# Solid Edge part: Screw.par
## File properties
Title: Screw
Author: Robert a Rhodes jr
Template: Normal.par
Last saved by: TIET
Revision: 10
Application: Solid Edge
Accuracy: 0.99
Material: aluminum
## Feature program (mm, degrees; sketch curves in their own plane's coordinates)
sketch for "unnamed Protrusion 1" plane through (0, 0, 0) normal (0, -1, 0) x-axis (1, 0, 0)
  circle centre (0, 0) radius 12.5
extrude "unnamed Protrusion 1" add finite 25 along +normal
sketch for "ExtrudedProtrusion_2" plane through (0, -25, 0) normal (0, -1, 0) x-axis (1, 0, 0)
  circle centre (0, 0) radius 10
extrude "ExtrudedProtrusion_2" add finite 96 along +normal
sketch for "ExtrudedProtrusion_3" plane through (0, -121, 0) normal (0, -1, 0) x-axis (1, 0, 0)
  circle centre (0, 0) radius 6
extrude "ExtrudedProtrusion_3" add finite 4 along +normal
sketch for "ExtrudedProtrusion_4" plane through (0, -125, 0) normal (0, -1, 0) x-axis (1, 0, 0)
  circle centre (0, 0) radius 4
extrude "ExtrudedProtrusion_4" add finite 6 along +normal
sketch for "unnamed RevolvedProtrusion 1" plane through (0, 0, 0) normal (0, 0, 1) x-axis (1, 0, 0)
  line (0, -131) -> (6, -131)
  line (6, -131) -> (6, -141)
  line (6, -141) -> (0, -143.8522)
  line (0, -143.8522) -> (0, -131)
revolve "unnamed RevolvedProtrusion 1" add full turn 360 deg about sketch line (0, -131) -> (0, -106.3065)
sketch for "ExtrudedCutout_1" plane through (0, 0, 0) normal (1, 0, 0) x-axis (0, 1, 0)
  circle centre (-13, 0) radius 5.5
extrude "ExtrudedCutout_1" cut finite 222.1 symmetric
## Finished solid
Body 1: solid body, 12 faces, 12 edges, 1 vertex.
  Faces by surface: cylinder 6, plane 5, cone 1
  Edges by curve: circle 10, intersection 2
Bounding box of the edges (mm): 25.000 x 141.000 x 25.000, from (-12.5, -141, -12.5) to (12.5, 0, 12.5).
Cylindrical faces by radius (mm): R4 x1, R5.5 x1, R6 x2, R10 x1, R12.5 x1
Conical faces (half-angle, radius in mm at the cone's reference point): 64.5754 deg R6 x1
Planar faces by outward normal: +y 2, -y 3
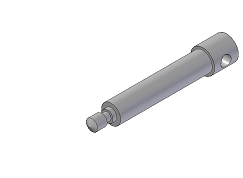
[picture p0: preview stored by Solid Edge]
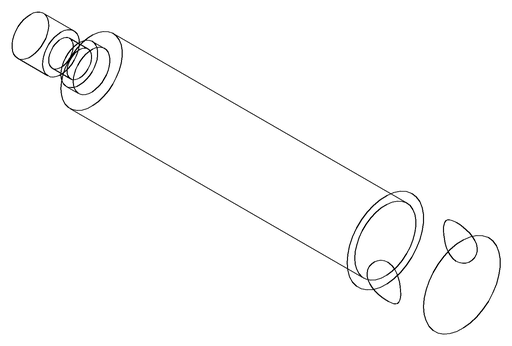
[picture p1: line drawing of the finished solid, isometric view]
